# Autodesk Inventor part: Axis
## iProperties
Created: 2001-11
Part Number: Axis
Document SubType Name: Modeling
Designer: Renu Muthoo
Control State: 0
Master: False
Checked Out: False
Shininess: 65.0
Length Units: 11269
Angle Units: 11279
Time Units: 11290
Mass Units: 11283
Length Display Precision: 3
Angle Display Precision: 2
Density: 0.0
Volumn: 0.0
Area: 0.0
PropertySet Name: Model Information
Author: Renu Muthoo
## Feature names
1. Revolution1
